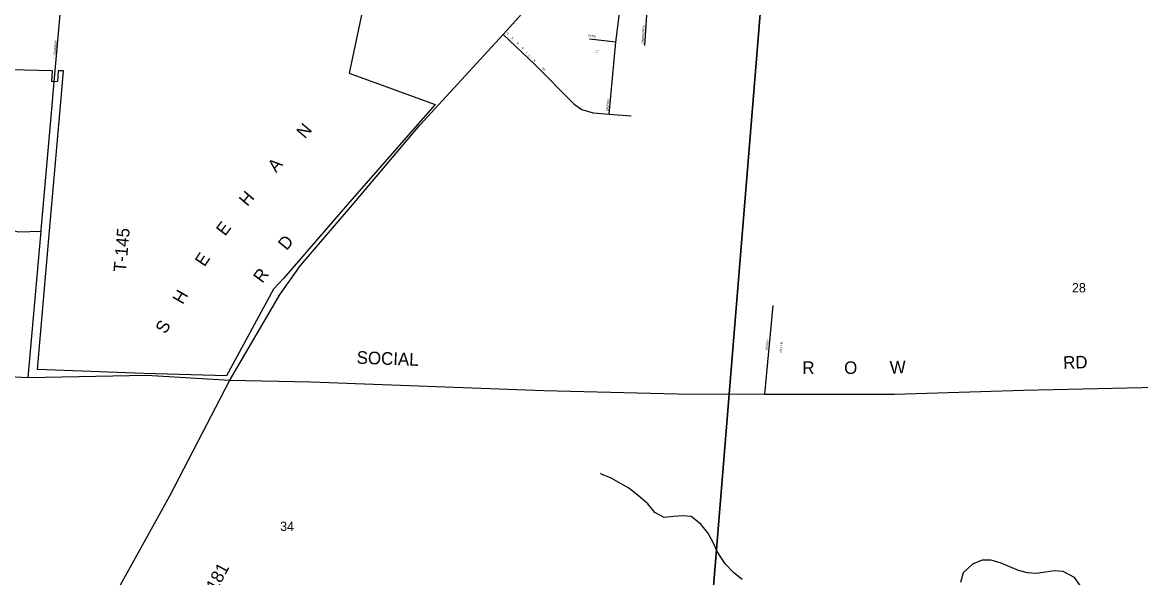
# Model space of a CAD drawing. Extents: x 1312308 to 1684953, y 460642 to 865172.
# Drawn here: x 1493271 to 1499914, y 582566 to 585863 of the extents above; entities that cross this region are included whole.
import ezdxf

# ---------------------------------------------------------------- set-up
doc = ezdxf.new("R2010")
doc.units = 0
for name, color, linetype in [('GM_X_City_Street', 7, 'Continuous'), ('GM_X_City_Street_Text', 7, 'Continuous'), ('GM_X_Corporation', 7, 'Continuous'), ('GM_X_County_Road', 7, 'Continuous'), ('GM_X_County_Road_Text', 7, 'Continuous'), ('GM_X_Minor_River', 7, 'Continuous'), ('GM_X_Section', 7, 'Continuous'), ('GM_X_Section_Text', 7, 'Continuous'), ('GM_X_Township_Road', 7, 'Continuous'), ('GM_X_Township_Road_Text', 7, 'Continuous'), ('GM_X_Township_Subdivision', 7, 'Continuous'), ('GM_X_Township_Subdivision_Text', 7, 'Continuous')]:
    doc.layers.add(name, color=color, linetype=linetype)

msp = doc.modelspace()

# ---------------------------------------------------------------- linework, layer by layer
at = {"layer": 'GM_X_City_Street'}
msp.add_lwpolyline([(1493454.1, 585442.1), (1493521.4, 586202.1), (1493537.4, 586386.2), (1493541.9, 586438.7), (1493560.1, 586649.1), (1493560.7, 586655.1)], dxfattribs=at)
at = {"layer": 'GM_X_Corporation'}
msp.add_lwpolyline([(1495309.5, 586019.8), (1495212, 585561.1), (1495722.8, 585375.1), (1495594.7, 585228.2), (1495214.9, 584794.6), (1494821.3, 584341.9), (1494762.2, 584278.8), (1494483.1, 583764.2), (1493992.3, 583778.1), (1493360.3, 583802.4), (1493432.8, 584625.6), (1493499.6, 585388.6), (1493516.1, 585574.7), (1493483.9, 585575.4), (1493480.5, 585511.4), (1493446.5, 585509.8), (1493449.9, 585576.1), (1493115.5, 585583.1)], dxfattribs=at)
at = {"layer": 'GM_X_County_Road'}
for points in [[(1494504, 583739.4), (1494504, 583739.4), (1494803.1, 584249.3), (1494923.5, 584419.9), (1495231.3, 584780), (1495631, 585253.4), (1496127.7, 585791.6), (1496612.5, 586331.6)], [(1490571, 584462.7), (1490609.7, 584430.2), (1491335.3, 584081.2), (1491425, 584055.3), (1491809.5, 583944.5), (1492026.4, 583826.7), (1492698.3, 583786.7), (1493305.9, 583754.5), (1494009, 583768.2), (1494504, 583739.4), (1494984.7, 583728.6), (1496369.1, 583676.4), (1497161.2, 583658.4), (1497681.1, 583656.4), (1497967.1, 583656.4), (1498451.3, 583656.4), (1499217, 583679.4), (1500099.5, 583699)], [(1492956.2, 580980.1), (1493027.7, 581047.7), (1493089.8, 581144.7), (1493327, 581571.2), (1493551.8, 581975.9), (1493822.4, 582465.9), (1494147.1, 583051.1), (1494504, 583739.4)]]:
    msp.add_lwpolyline(points, dxfattribs=at)
at = {"layer": 'GM_X_Minor_River'}
for points in [[(1497083.6, 582922.2), (1497028.3, 582952), (1496985.7, 583003.6), (1496930.9, 583051.4), (1496874.1, 583097.4), (1496767.5, 583156.9), (1496711.9, 583180.7), (1496706.1, 583186.9)], [(1497546.4, 582554.5), (1497495.4, 582596.3), (1497444.8, 582648), (1497398.9, 582721.7), (1497374.4, 582774.7), (1497342, 582831.9), (1497301.4, 582883.3), (1497244.6, 582929.3), (1497194.5, 582932.8), (1497138.1, 582928.6), (1497083.6, 582922.2)], [(1499560.4, 582512.1), (1499519.9, 582567.5), (1499452.6, 582601.8), (1499400.6, 582607.4), (1499348.1, 582599), (1499293.6, 582590.6), (1499241.4, 582594.3), (1499187.6, 582608), (1499084.5, 582651.3), (1499024.8, 582669.2), (1498972.6, 582670.8), (1498915.5, 582646.5), (1498859.7, 582594.1), (1498843.8, 582536.3)]]:
    msp.add_lwpolyline(points, dxfattribs=at)
at = {"layer": 'GM_X_Section'}
for points in [[(1497694, 586401.3), (1502978, 586568.2), (1502584.5, 581040.7), (1497239.8, 580838.9)], [(1492253.1, 586509.3), (1497694, 586401.3), (1497239.8, 580838.9), (1491791, 581160.9)]]:
    msp.add_lwpolyline(points, close=True, dxfattribs=at)
at = {"layer": 'GM_X_Township_Road'}
msp.add_lwpolyline([(1493305.9, 583754.5), (1493382.4, 584623.1), (1493383, 584630), (1493449.8, 585393), (1493454.1, 585442.1)], dxfattribs=at)
at = {"layer": 'GM_X_Township_Subdivision'}
for points in [[(1496757, 585318.8), (1496795.5, 585745.7), (1496823.4, 585966), (1496819.9, 586059.5), (1496804.7, 586112.2), (1496789.3, 586151.3), (1496748.5, 586207.5), (1496612.5, 586331.6)], [(1496967.7, 585725.7), (1497003.6, 586268.7)], [(1496127.7, 585791.6), (1496313.1, 585614.7), (1496549.5, 585377.5), (1496593.8, 585346), (1496661.8, 585325.6), (1496757, 585318.8), (1496887.9, 585308)], [(1496795.5, 585745.7), (1496638.8, 585763.6)], [(1492244.2, 584714), (1492420.1, 584703.3), (1492676, 584685.5), (1493063.4, 584667.8), (1493148, 584642), (1493249.9, 584619.8), (1493382.4, 584623.1)], [(1497681.1, 583656.4), (1497730, 584182.1)]]:
    msp.add_lwpolyline(points, dxfattribs=at)

# ---------------------------------------------------------------- texts
at = {"layer": 'GM_X_City_Street_Text'}
msp.add_text('PARAGON', height=12.5, rotation=84.88219, dxfattribs=at).set_placement((1493468.3, 585668.6))
at = {"layer": 'GM_X_County_Road_Text'}
for s, rotation, p in [('N', 49.62319, (1494949.2, 585168.3)), ('A', 49.62352, (1494778.2, 584967.2)), ('H', 49.66738, (1494607.4, 584766)), ('E', 53.04781, (1494475.4, 584590.3)), ('D', 50.67342, (1494840.9, 584504.8)), ('E', 56.06745, (1494352.6, 584407.5)), ('R', 53.4673, (1494696.6, 584309.9)), ('H', 59.90494, (1494223, 584183.6)), ('S', 59.90739, (1494121.5, 584008.5)), ('SOCIAL', 357.92015, (1495255.7, 583836.5)), ('RD', 1.48157, (1499454.2, 583805.6)), ('R', 0.00195, (1497904, 583775)), ('O', 0.39794, (1498152.7, 583775)), ('W', 1.81198, (1498424.8, 583777)), ('C-181', 61.71842, (1494373.2, 582387.3))]:
    msp.add_text(s, height=75, rotation=rotation, dxfattribs=at).set_placement(p)
at = {"layer": 'GM_X_Section_Text'}
for s, p in [('28', (1499505.6, 584260)), ('34', (1494802, 582843.2))]:
    msp.add_text(s, height=55.25, rotation=0.00001, dxfattribs=at).set_placement(p)
at = {"layer": 'GM_X_Township_Road_Text'}
msp.add_text('T-145', height=75, rotation=84.95771, dxfattribs=at).set_placement((1493886.4, 584378.1))
at = {"layer": 'GM_X_Township_Subdivision_Text'}
for s, rotation, p in [('CHEDWORTH', 86.78622, (1496961.8, 585734.2)), ('C', 314.40758, (1496146.4, 585797.5)), ('A', 314.40488, (1496174.1, 585769.2)), ('R', 314.40758, (1496204.9, 585737.7)), ('BYRD', 354.14463, (1496629, 585778.2)), ('R', 314.40758, (1496232.6, 585709.4)), ('I', 314.39254, (1496260.3, 585681.2)), ('CT', 356.81546, (1496672.2, 585683.6)), ('C', 314.41739, (1496275.7, 585665.4)), ('K', 317.77391, (1496305.7, 585634.9)), ('DR', 315, (1496353.1, 585590.7)), ('SAWTRY', 84.19643, (1496750.7, 585334.3)), ('WATCH', 84.40377, (1497696.7, 583917.4)), ('HILL LN', 84.71288, (1497781.4, 583900.7))]:
    msp.add_text(s, height=12.5, rotation=rotation, dxfattribs=at).set_placement(p)

doc.saveas('drawing.dxf')
